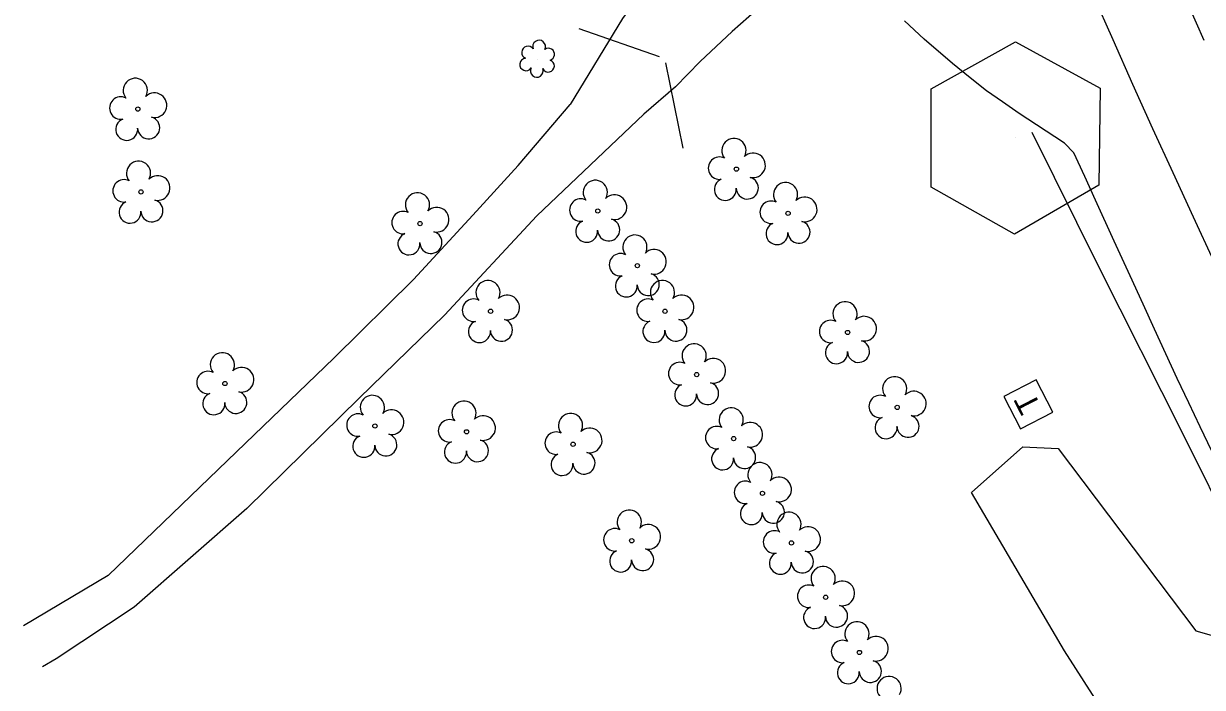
# Model space of a CAD drawing. Extents: x 477009 to 479892, y 492858 to 496862.
# Drawn here: x 478413.8 to 478595, y 494537.6 to 494639.8 of the extents above; entities that cross this region are included whole.
import ezdxf

# ---------------------------------------------------------------- set-up
doc = ezdxf.new("R2010")
doc.units = 0
for name, color, linetype in [('CTL Primary Horizontal and Vertical CELL', 7, 'Continuous'), ('Exist Guardrail', 7, 'Continuous'), ('Exist Horizontal Alignment', 7, 'Continuous'), ('Exist Other Culture Gate', 7, 'Continuous'), ('Exist Roads EOP', 7, 'Continuous'), ('Exist Roads Soil', 7, 'Continuous'), ('Exist Utilities Telephone Pedestal CELL', 7, 'Continuous'), ('Exist Vegetation Hedge Row', 7, 'Continuous'), ('Exist Vegetation Shrub CELL', 7, 'Continuous'), ('Exist Vegetation Tree CELL', 7, 'Continuous')]:
    doc.layers.add(name, color=color, linetype=linetype)

msp = doc.modelspace()

# ---------------------------------------------------------------- linework, layer by layer
at = {"layer": 'CTL Primary Horizontal and Vertical CELL'}
msp.add_line((478566.19, 494622.23), (478566.19, 494622.23), dxfattribs=at)
msp.add_lwpolyline([(478553.27, 494629.71), (478566.27, 494636.96), (478579.27, 494629.81), (478579.07, 494614.91), (478566.07, 494607.36), (478553.27, 494614.61)], close=True, dxfattribs=at)
at = {"layer": 'Exist Guardrail'}
msp.add_lwpolyline([(478848.96, 494173.09), (478823.38, 494205.51), (478797.42, 494239.12), (478772.09, 494273.2), (478749.01, 494305.94), (478733.03, 494329.58), (478715.27, 494357.24), (478689.75, 494398.3), (478671.1, 494429.57), (478654.66, 494457.42), (478638.8, 494486.1), (478625.46, 494510.7), (478608.27, 494543.89), (478591.97, 494576.68), (478579.13, 494602.21), (478568.8, 494623)], dxfattribs=at)
at = {"layer": 'Exist Horizontal Alignment'}
msp.add_arc((480407.9, 495448.91), 1998.89, 192.1328, 219.63873, dxfattribs=at)
at = {"layer": 'Exist Other Culture Gate'}
for p, q in [((478499.14, 494639), (478511.49, 494634.7)), ((478512.44, 494633.72), (478515.1, 494620.58))]:
    msp.add_line(p, q, dxfattribs=at)
at = {"layer": 'Exist Roads EOP'}
for points in [[(478595.23, 494637.16), (478592.88, 494642.47)], [(478596.42, 494573.98), (478594.63, 494577.71), (478592.87, 494581.44), (478591.12, 494585.18), (478589.36, 494588.96), (478587.61, 494592.77), (478585.85, 494596.61), (478583.87, 494600.96), (478581.43, 494606.29), (478578.55, 494612.59), (478576.89, 494616.23), (478575.22, 494619.87), (478573.76, 494621.36), (478569.45, 494624.18), (478566.83, 494625.92), (478564.24, 494627.69), (478561.8, 494629.43), (478559.26, 494631.39), (478556.57, 494633.61), (478552.22, 494637.37), (478549.16, 494640.17)]]:
    msp.add_lwpolyline(points, dxfattribs=at)
at = {"layer": 'Exist Roads Soil'}
for points in [[(478527.01, 494667.9), (478521.57, 494661.84), (478514.34, 494652.28), (478505.82, 494640.55), (478497.77, 494627.29)], [(478538.91, 494650.21), (478535.2, 494648.28), (478530.02, 494645.03), (478525.25, 494640.79), (478522.68, 494638.52), (478517.75, 494633.9), (478513.99, 494630), (478509.1, 494625.83)], [(478426.78, 494554.87), (478446.5, 494573.87), (478461.48, 494588.3), (478473.68, 494600.41), (478482.81, 494610.3), (478489.81, 494617.94), (478497.77, 494627.29)], [(478509.1, 494625.83), (478492.69, 494610.18), (478478.48, 494594.9), (478465.36, 494582.13), (478448.1, 494565.15), (478430.75, 494549.97)], [(478426.78, 494554.87), (478413.77, 494547.1)], [(478430.75, 494549.97), (478418.77, 494542.02), (478416.69, 494540.79)]]:
    msp.add_lwpolyline(points, dxfattribs=at)
at = {"layer": 'Exist Utilities Telephone Pedestal CELL'}
msp.add_line((478568.21, 494581.1), (478568.21, 494581.1), dxfattribs=at)
msp.add_lwpolyline([(478571.97, 494579.96), (478569.41, 494584.94), (478564.44, 494582.39), (478566.99, 494577.41), (478571.97, 494579.96)], dxfattribs=at)
at = {"layer": 'Exist Vegetation Hedge Row'}
msp.add_lwpolyline([(478708.38, 494326.9), (478687.37, 494360.79), (478664.7, 494392.81), (478641.97, 494432.3), (478623.26, 494469.49), (478605.12, 494499.9), (478588.1, 494520.99), (478573.76, 494543.26), (478559.5, 494567.63), (478567.36, 494574.63), (478572.8, 494574.41), (478593.95, 494546.36), (478604.93, 494543.22), (478641.84, 494473.22), (478682.21, 494404.4), (478713.16, 494353.28), (478739.04, 494313.7)], dxfattribs=at)
at = {"layer": 'Exist Vegetation Shrub CELL'}
msp.add_line((478492.79, 494634.16), (478492.79, 494634.16), dxfattribs=at)
for centre, radius, start, end in [((478493.02, 494636.2), 0.99, 334.8391, 200.4717), ((478491.31, 494635.29), 0.968, 35.8908, 245.4216), ((478494.46, 494635.03), 0.929, 284.4567, 126.0861), ((478490.99, 494633.46), 0.955, 95.1099, 327.9534), ((478494.43, 494633.23), 0.937, 204.9913, 73.4601), ((478492.66, 494632.48), 0.984, 151.2797, 21.387)]:
    msp.add_arc(centre, radius, start, end, dxfattribs=at)
at = {"layer": 'Exist Vegetation Tree CELL'}
for p, q in [((478431.33, 494626.6), (478431.33, 494626.6)), ((478523.35, 494617.36), (478523.35, 494617.36)), ((478431.82, 494613.86), (478431.82, 494613.86)), ((478502.04, 494610.92), (478502.04, 494610.92)), ((478531.29, 494610.57), (478531.29, 494610.57)), ((478474.71, 494608.99), (478474.71, 494608.99)), ((478508.12, 494602.51), (478508.12, 494602.51)), ((478485.55, 494595.5), (478485.55, 494595.5)), ((478512.36, 494595.51), (478512.36, 494595.51)), ((478540.43, 494592.24), (478540.43, 494592.24)), ((478444.72, 494584.39), (478444.72, 494584.39)), ((478517.24, 494585.76), (478517.24, 494585.76)), ((478548.06, 494580.71), (478548.06, 494580.71)), ((478467.77, 494577.85), (478467.77, 494577.85)), ((478481.86, 494576.96), (478481.86, 494576.96)), ((478498.24, 494575.05), (478498.24, 494575.05)), ((478522.92, 494575.92), (478522.92, 494575.92)), ((478527.35, 494567.5), (478527.35, 494567.5)), ((478507.25, 494560.21), (478507.25, 494560.21)), ((478531.81, 494559.87), (478531.81, 494559.87)), ((478537.06, 494551.52), (478537.06, 494551.52)), ((478542.25, 494543.02), (478542.25, 494543.02))]:
    msp.add_line(p, q, dxfattribs=at)
for centre in [(478431.33, 494626.6), (478523.35, 494617.36), (478431.82, 494613.86), (478502.04, 494610.92), (478531.29, 494610.57), (478474.71, 494608.99), (478508.12, 494602.51), (478485.55, 494595.5), (478512.36, 494595.51), (478540.43, 494592.24), (478517.24, 494585.76), (478444.72, 494584.39), (478548.06, 494580.71), (478467.77, 494577.85), (478481.86, 494576.96), (478498.24, 494575.05), (478522.92, 494575.92), (478527.35, 494567.5), (478507.25, 494560.21), (478531.81, 494559.87), (478537.06, 494551.52), (478542.25, 494543.02)]:
    msp.add_circle(centre, 0.326, dxfattribs=at)
for centre, radius, start, end in [((478430.94, 494629.48), 1.86, 330.1651, 219.7134), ((478428.72, 494626.76), 1.73, 62.6636, 279.3457), ((478433.88, 494627.19), 1.9, 257.1011, 134.1999), ((478429.62, 494623.48), 1.69, 111.5671, 6.231), ((478433, 494623.71), 1.7, 181.2822, 74.56), ((478522.96, 494620.23), 1.86, 330.1651, 219.7134), ((478431.44, 494616.73), 1.86, 330.1651, 219.7134), ((478520.74, 494617.51), 1.73, 62.6636, 279.3457), ((478525.9, 494617.95), 1.9, 257.1011, 134.1999), ((478429.21, 494614.02), 1.73, 62.6636, 279.3457), ((478434.37, 494614.45), 1.9, 257.1011, 134.1999), ((478501.65, 494613.79), 1.86, 330.1651, 219.7134), ((478521.64, 494614.24), 1.69, 111.5671, 6.231), ((478525.02, 494614.46), 1.7, 181.2822, 74.56), ((478530.9, 494613.45), 1.86, 330.1651, 219.7134), ((478474.32, 494611.86), 1.86, 330.1651, 219.7134), ((478504.59, 494611.51), 1.9, 257.1011, 134.1999), ((478533.84, 494611.16), 1.9, 257.1011, 134.1999), ((478430.12, 494610.74), 1.69, 111.5671, 6.231), ((478433.49, 494610.96), 1.7, 181.2822, 74.56), ((478477.26, 494609.58), 1.9, 257.1011, 134.1999), ((478499.43, 494611.07), 1.73, 62.6636, 279.3457), ((478528.68, 494610.73), 1.73, 62.6636, 279.3457), ((478472.1, 494609.14), 1.73, 62.6636, 279.3457), ((478503.71, 494608.02), 1.7, 181.2822, 74.56), ((478476.38, 494606.09), 1.7, 181.2822, 74.56), ((478500.33, 494607.8), 1.69, 111.5671, 6.231), ((478529.58, 494607.45), 1.69, 111.5671, 6.231), ((478532.96, 494607.67), 1.7, 181.2822, 74.56), ((478473, 494605.87), 1.69, 111.5671, 6.231), ((478507.74, 494605.38), 1.86, 330.1651, 219.7134), ((478505.52, 494602.66), 1.73, 62.6636, 279.3457), ((478510.67, 494603.1), 1.9, 257.1011, 134.1999), ((478506.42, 494599.39), 1.69, 111.5671, 6.231), ((478509.79, 494599.61), 1.7, 181.2822, 74.56), ((478485.16, 494598.37), 1.86, 330.1651, 219.7134), ((478511.98, 494598.38), 1.86, 330.1651, 219.7134), ((478482.94, 494595.66), 1.73, 62.6636, 279.3457), ((478488.1, 494596.09), 1.9, 257.1011, 134.1999), ((478509.76, 494595.67), 1.73, 62.6636, 279.3457), ((478514.91, 494596.1), 1.9, 257.1011, 134.1999), ((478540.05, 494595.11), 1.86, 330.1651, 219.7134), ((478483.84, 494592.38), 1.69, 111.5671, 6.231), ((478487.22, 494592.6), 1.7, 181.2822, 74.56), ((478510.66, 494592.39), 1.69, 111.5671, 6.231), ((478514.04, 494592.61), 1.7, 181.2822, 74.56), ((478537.83, 494592.39), 1.73, 62.6636, 279.3457), ((478542.98, 494592.83), 1.9, 257.1011, 134.1999), ((478516.85, 494588.64), 1.86, 330.1651, 219.7134), ((478538.73, 494589.12), 1.69, 111.5671, 6.231), ((478542.11, 494589.34), 1.7, 181.2822, 74.56), ((478444.33, 494587.27), 1.86, 330.1651, 219.7134), ((478519.79, 494586.35), 1.9, 257.1011, 134.1999), ((478442.11, 494584.55), 1.73, 62.6636, 279.3457), ((478447.27, 494584.98), 1.9, 257.1011, 134.1999), ((478514.63, 494585.92), 1.73, 62.6636, 279.3457), ((478515.54, 494582.64), 1.69, 111.5671, 6.231), ((478518.91, 494582.86), 1.7, 181.2822, 74.56), ((478547.67, 494583.58), 1.86, 330.1651, 219.7134), ((478443.01, 494581.27), 1.69, 111.5671, 6.231), ((478446.39, 494581.49), 1.7, 181.2822, 74.56), ((478467.39, 494580.72), 1.86, 330.1651, 219.7134), ((478545.45, 494580.86), 1.73, 62.6636, 279.3457), ((478550.61, 494581.3), 1.9, 257.1011, 134.1999), ((478481.47, 494579.83), 1.86, 330.1651, 219.7134), ((478522.54, 494578.79), 1.86, 330.1651, 219.7134), ((478465.17, 494578), 1.73, 62.6636, 279.3457), ((478470.32, 494578.44), 1.9, 257.1011, 134.1999), ((478479.25, 494577.11), 1.73, 62.6636, 279.3457), ((478484.4, 494577.54), 1.9, 257.1011, 134.1999), ((478497.85, 494577.93), 1.86, 330.1651, 219.7134), ((478546.35, 494577.59), 1.69, 111.5671, 6.231), ((478549.73, 494577.81), 1.7, 181.2822, 74.56), ((478495.63, 494575.21), 1.73, 62.6636, 279.3457), ((478500.79, 494575.64), 1.9, 257.1011, 134.1999), ((478520.32, 494576.07), 1.73, 62.6636, 279.3457), ((478525.47, 494576.51), 1.9, 257.1011, 134.1999), ((478466.07, 494574.73), 1.69, 111.5671, 6.231), ((478469.45, 494574.95), 1.7, 181.2822, 74.56), ((478480.15, 494573.83), 1.69, 111.5671, 6.231), ((478483.53, 494574.06), 1.7, 181.2822, 74.56), ((478496.53, 494571.93), 1.69, 111.5671, 6.231), ((478499.91, 494572.16), 1.7, 181.2822, 74.56), ((478521.22, 494572.8), 1.69, 111.5671, 6.231), ((478524.6, 494573.02), 1.7, 181.2822, 74.56), ((478526.96, 494570.37), 1.86, 330.1651, 219.7134), ((478529.9, 494568.09), 1.9, 257.1011, 134.1999), ((478524.74, 494567.65), 1.73, 62.6636, 279.3457), ((478525.64, 494564.38), 1.69, 111.5671, 6.231), ((478529.02, 494564.6), 1.7, 181.2822, 74.56), ((478506.87, 494563.08), 1.86, 330.1651, 219.7134), ((478531.42, 494562.74), 1.86, 330.1651, 219.7134), ((478509.8, 494560.8), 1.9, 257.1011, 134.1999), ((478534.36, 494560.46), 1.9, 257.1011, 134.1999), ((478504.65, 494560.36), 1.73, 62.6636, 279.3457), ((478529.2, 494560.02), 1.73, 62.6636, 279.3457), ((478505.55, 494557.09), 1.69, 111.5671, 6.231), ((478508.93, 494557.31), 1.7, 181.2822, 74.56), ((478530.1, 494556.75), 1.69, 111.5671, 6.231), ((478533.48, 494556.97), 1.7, 181.2822, 74.56), ((478536.68, 494554.39), 1.86, 330.1651, 219.7134), ((478534.46, 494551.67), 1.73, 62.6636, 279.3457), ((478539.61, 494552.11), 1.9, 257.1011, 134.1999), ((478535.36, 494548.4), 1.69, 111.5671, 6.231), ((478538.73, 494548.62), 1.7, 181.2822, 74.56), ((478541.87, 494545.89), 1.86, 330.1651, 219.7134), ((478539.65, 494543.17), 1.73, 62.6636, 279.3457), ((478544.8, 494543.61), 1.9, 257.1011, 134.1999), ((478540.55, 494539.9), 1.69, 111.5671, 6.231), ((478543.93, 494540.12), 1.7, 181.2822, 74.56), ((478546.82, 494537.47), 1.86, 330.1651, 219.7134)]:
    msp.add_arc(centre, radius, start, end, dxfattribs=at)

# ---------------------------------------------------------------- texts
at = {"layer": 'Exist Utilities Telephone Pedestal CELL'}
msp.add_text('T', height=3.42, rotation=117.17, dxfattribs=at).set_placement((478570.25, 494580.87))

doc.saveas('drawing.dxf')
